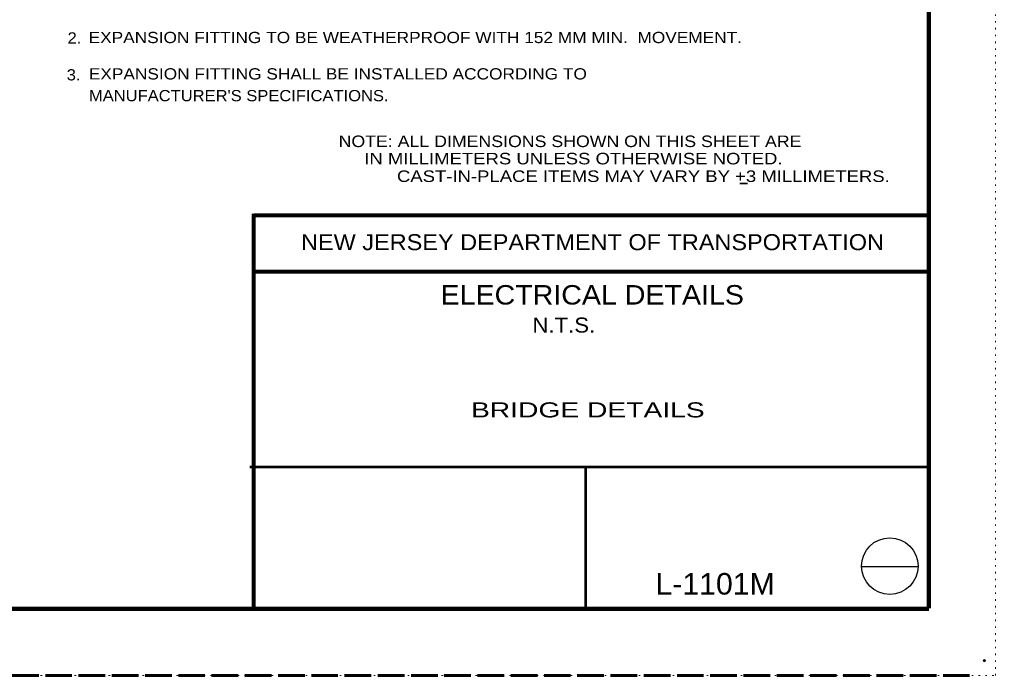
# Model space of a CAD drawing. Extents: x 312583 to 312854, y 144419 to 144597.
# Drawn here: x 312787.5 to 312853.5, y 144418.6 to 144463 of the extents above; entities that cross this region are included whole.
import ezdxf
from ezdxf.enums import TextEntityAlignment as Align

# ---------------------------------------------------------------- set-up
doc = ezdxf.new("R2010")
doc.units = 0
doc.header["$LTSCALE"] = 0.3
doc.header["$PDMODE"] = 32
doc.header["$PDSIZE"] = 0.15
doc.linetypes.add('DOTTED', pattern=[1.5, 0.3, -1.2])
doc.linetypes.add('LONG_DASHED', pattern=[7.5, 6, -1.5])
doc.layers.add('1', color=7, linetype='Continuous', lineweight=13)
doc.layers.add('63', color=7, linetype='DOTTED', lineweight=13)
doc.layers.add('2', color=7, linetype='Continuous')
doc.layers.add('5', color=7, linetype='Continuous')

msp = doc.modelspace()

# ---------------------------------------------------------------- linework, layer by layer
at = {"layer": '1', "lineweight": 158}
for p, q in [((312849, 144423.1446), (312849, 144585.0846)), ((312616.5, 144423.0846), (312849, 144423.0846))]:
    msp.add_line(p, q, dxfattribs=at)
at = {"layer": '1', "lineweight": 35}
msp.add_line((312836.2036, 144451.8524), (312836.7135, 144451.8524), dxfattribs=at)
at = {"layer": '1', "lineweight": 80}
for p, q in [((312803.31, 144423.1446), (312803.31, 144449.8146)), ((312803.31, 144449.7246), (312849, 144449.7246)), ((312803.31, 144445.9146), (312849, 144445.9146))]:
    msp.add_line(p, q, dxfattribs=at)
at = {"layer": '1', "lineweight": 53}
for p, q in [((312849, 144432.6666), (312803.0384, 144432.6666)), ((312825.7547, 144432.6666), (312825.7547, 144423.1446))]:
    msp.add_line(p, q, dxfattribs=at)
at = {"layer": '1', "lineweight": 25}
msp.add_line((312844.4384, 144425.966), (312848.2794, 144425.966), dxfattribs=at)
at = {"layer": '1', "linetype": 'LONG_DASHED', "lineweight": 60}
msp.add_line((312851.75, 144418.5846), (312583.526, 144418.5846), dxfattribs=at)
at = {"layer": '1', "linetype": 'DOTTED'}
msp.add_line((312601.2, 144418.5846), (312853.5, 144418.5846), dxfattribs=at)
at = {"layer": '1', "lineweight": 25}
msp.add_circle((312846.3494, 144425.9805), 1.9159, dxfattribs=at)
at = {"layer": '1'}
msp.add_point((312852.75, 144419.5846), dxfattribs=at)
at = {"layer": '63'}
msp.add_line((312853.5, 144418.5846), (312853.5, 144596.7846), dxfattribs=at)

# ---------------------------------------------------------------- texts
at = {"layer": '1'}
for s, height, width, p in [('2.  ', 0.76, 1.1, (312790.7016, 144461.3298)), ('EXPANSION FITTING TO BE WEATHERPROOF WITH 152 MM MIN.  MOVEMENT.', 0.76, 1.15, (312792.1281, 144461.3605)), ('EXPANSION FITTING SHALL BE INSTALLED ACCORDING TO', 0.76, 1.15, (312792.1435, 144458.8995)), ('3.  ', 0.76, 1.1, (312790.646, 144458.8363)), ("MANUFACTURER'S SPECIFICATIONS.", 0.76, 1.1, (312792.1511, 144457.4275)), ('NOTE: ALL DIMENSIONS SHOWN ON THIS SHEET ARE', 0.78, 1.15, (312809.0457, 144454.3276)), ('     IN MILLIMETERS UNLESS OTHERWISE NOTED.', 0.78, 1.2, (312809.0456, 144453.1576)), ('CAST-IN-PLACE ITEMS MAY VARY BY +3 MILLIMETERS.', 0.78, 1.2, (312812.9965, 144451.9667))]:
    msp.add_text(s, height=height, dxfattribs=dict(at, width=width)).set_placement(p)
at = {"layer": '1', "width": 1.1}
for s, height, p in [('NEW JERSEY DEPARTMENT OF TRANSPORTATION', 1.08, (312826.2285, 144447.3546)), ('ELECTRICAL DETAILS', 1.315, (312826.2109, 144443.676))]:
    msp.add_text(s, height=height, dxfattribs=at).set_placement(p, align=Align.CENTER)
at = {"layer": '2'}
for s, width, p in [('    N.T.S.  ', 1.1, (312823.87, 144441.778)), ('               BRIDGE DETAILS               ', 1.4, (312825.9119, 144436.04))]:
    msp.add_text(s, height=1.02, dxfattribs=dict(at, width=width)).set_placement(p, align=Align.CENTER)
at = {"layer": '5', "width": 1.05}
msp.add_text('L-1101M  ', height=1.457, dxfattribs=at).set_placement((312835.0944, 144424.057), align=Align.CENTER)

doc.saveas('drawing.dxf')
